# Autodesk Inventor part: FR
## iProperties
Created: 2007-03
Part Number: FR
Cost Center: 44,77 kg
Material: S235JRG2
Document SubType Name: Modeling
Designer: Chako
Authority: 5702676,4 mm^3
SaveDate: 2007-03-16
SaveTime: 17:26
FileName: FR
TotalMass: 44,77 kg
TotalVolume: 5702676,4 mm^3
Author: Chako
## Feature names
1. Extrusion2
2. Rundung1 [Fillet]
3. Wandstärke1
